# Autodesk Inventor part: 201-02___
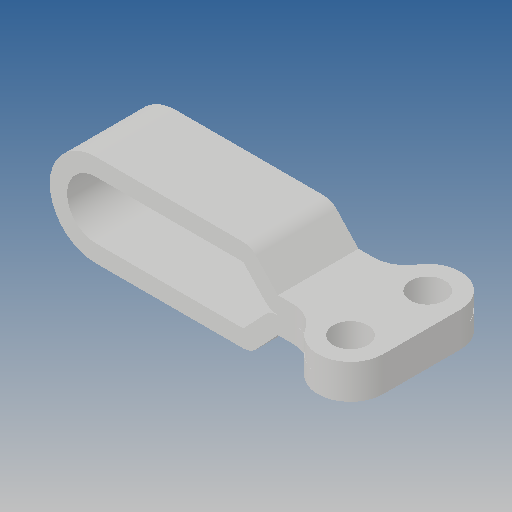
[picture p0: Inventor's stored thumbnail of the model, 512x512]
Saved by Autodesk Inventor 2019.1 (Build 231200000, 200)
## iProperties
Created: 2010-06
Part Number: 201-02___
Material: Ogólny
Document SubType Name: Modeling
Designer: CADENGINEERING4
Density: 1 g/cm^3
Appearance: Domyślna
Author: CADENGINEERING4
Revision Number: ANY
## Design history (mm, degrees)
feature "NONE"
feature "NONE:1"
node "Bryła1"
node "Bryła2"
